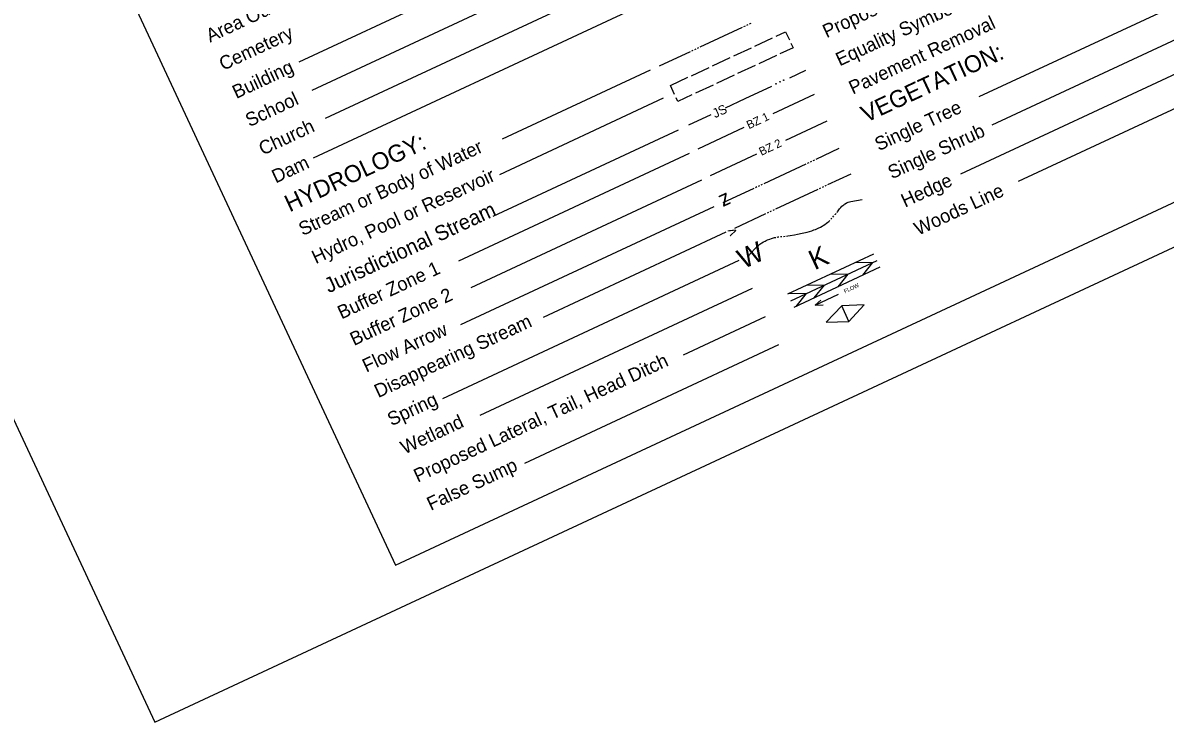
# Model space of a CAD drawing. Extents: x 885291.5 to 885341.7, y 651350.6 to 651393.5.
# Drawn here: x 885301.03 to 885319.4, y 651350.6 to 651361.84 of the extents above; entities that cross this region are included whole.
import ezdxf

# ---------------------------------------------------------------- set-up
doc = ezdxf.new("R2010")
doc.units = 0
doc.layers.add('Sheet Symbology CELL', color=7, linetype='Continuous')
doc.layers.add('Stewart Plot Border Xerox6279 and LJ5000', color=7, linetype='Continuous')

msp = doc.modelspace()

# ---------------------------------------------------------------- linework, layer by layer
at = {"layer": 'Sheet Symbology CELL'}
for p, q in [((885310.171, 651363.407), (885305.464, 651361.212)), ((885310.382, 651362.954), (885305.676, 651360.759)), ((885310.593, 651362.5), (885305.887, 651360.306)), ((885320.502, 651362.567), (885316.398, 651360.653)), ((885320.713, 651362.113), (885316.61, 651360.2)), ((885310.805, 651362.047), (885305.697, 651359.666)), ((885311.921, 651361.459), (885312.601, 651361.776)), ((885312.624, 651361.787), (885312.646, 651361.797)), ((885312.669, 651361.808), (885312.692, 651361.818)), ((885312.714, 651361.829), (885312.737, 651361.839)), ((885312.799, 651361.471), (885313.083, 651361.603)), ((885320.925, 651361.66), (885316.106, 651359.413)), ((885311.264, 651361.152), (885311.763, 651361.385)), ((885311.785, 651361.396), (885311.808, 651361.406)), ((885311.831, 651361.417), (885311.853, 651361.427)), ((885311.876, 651361.438), (885311.899, 651361.449)), ((885312.46, 651361.312), (885312.743, 651361.444)), ((885312.12, 651361.154), (885312.403, 651361.286)), ((885313.145, 651361.32), (885312.862, 651361.188)), ((885321.136, 651361.207), (885317.032, 651359.293)), ((885311.116, 651361.084), (885308.737, 651359.974)), ((885311.78, 651360.995), (885312.063, 651361.127)), ((885312.465, 651361.003), (885312.182, 651360.871)), ((885312.805, 651361.161), (885312.522, 651361.029)), ((885311.44, 651360.837), (885311.723, 651360.969)), ((885311.507, 651360.694), (885311.44, 651360.837)), ((885312.126, 651360.844), (885311.842, 651360.712)), ((885311.327, 651360.631), (885308.69, 651359.401)), ((885313.754, 651360.692), (885313.09, 651360.383)), ((885313.954, 651360.262), (885313.29, 651359.953)), ((885311.566, 651360.119), (885308.584, 651358.728)), ((885311.885, 651359.821), (885312.628, 651360.167)), ((885311.742, 651359.742), (885308.031, 651358.012)), ((885312.085, 651359.391), (885312.828, 651359.737)), ((885313.784, 651359.653), (885314.157, 651359.827)), ((885312.946, 651359.262), (885313.625, 651359.579)), ((885313.648, 651359.59), (885313.671, 651359.6)), ((885313.693, 651359.611), (885313.716, 651359.622)), ((885313.739, 651359.632), (885313.761, 651359.643)), ((885313.975, 651359.243), (885314.349, 651359.417)), ((885311.941, 651359.314), (885308.231, 651357.584)), ((885312.288, 651358.956), (885312.787, 651359.188)), ((885312.81, 651359.199), (885312.832, 651359.21)), ((885312.855, 651359.22), (885312.878, 651359.231)), ((885312.9, 651359.241), (885312.923, 651359.252)), ((885313.137, 651358.852), (885313.817, 651359.169)), ((885313.839, 651359.179), (885313.862, 651359.19)), ((885313.885, 651359.201), (885313.907, 651359.211)), ((885313.93, 651359.222), (885313.953, 651359.232)), ((885312.14, 651358.887), (885308.066, 651356.987)), ((885312.479, 651358.545), (885312.978, 651358.778)), ((885313.001, 651358.788), (885313.024, 651358.799)), ((885313.046, 651358.81), (885313.069, 651358.82)), ((885313.092, 651358.831), (885313.114, 651358.841)), ((885314.02, 651358.685), (885314.037, 651358.703)), ((885314.054, 651358.721), (885314.071, 651358.74)), ((885312.332, 651358.476), (885309.397, 651357.108)), ((885313.259, 651358.411), (885313.284, 651358.414)), ((885313.331, 651357.487), (885314.713, 651358.132)), ((885312.543, 651358.023), (885307.774, 651355.799)), ((885313.375, 651357.376), (885314.764, 651358.023)), ((885313.43, 651357.273), (885314.813, 651357.918)), ((885314.425, 651357.997), (885314.693, 651357.99)), ((885314.693, 651357.99), (885314.531, 651357.786)), ((885314.023, 651357.81), (885314.296, 651357.805)), ((885314.296, 651357.805), (885314.131, 651357.6)), ((885312.754, 651357.57), (885308.377, 651355.529)), ((885313.351, 651357.497), (885313.623, 651357.491)), ((885313.623, 651357.491), (885313.457, 651357.285)), ((885313.639, 651357.631), (885313.912, 651357.626)), ((885313.912, 651357.626), (885313.746, 651357.42)), ((885313.767, 651357.306), (885314.144, 651357.482)), ((885313.767, 651357.306), (885313.861, 651357.387)), ((885313.767, 651357.306), (885313.896, 651357.312)), ((885314.555, 651357.309), (885314.195, 651357.293)), ((885314.312, 651357.043), (885314.555, 651357.309)), ((885314.195, 651357.293), (885313.943, 651357.03)), ((885314.312, 651357.043), (885314.195, 651357.293)), ((885312.966, 651357.117), (885311.648, 651356.502)), ((885313.943, 651357.03), (885314.312, 651357.043)), ((885313.177, 651356.664), (885309.092, 651354.759))]:
    msp.add_line(p, q, dxfattribs=at)
msp.add_lwpolyline([(885329.923, 651392.736), (885295.937, 651376.888), (885307.02, 651353.12), (885341.006, 651368.969)], close=True, dxfattribs=at)
for points in [[(885313.139, 651361.629), (885313.294, 651361.701), (885313.354, 651361.573)], [(885313.38, 651361.516), (885313.414, 651361.445), (885313.202, 651361.346)], [(885313.359, 651360.96), (885313.618, 651361.081)], [(885312.643, 651360.626), (885313.074, 651360.827)], [(885311.786, 651360.686), (885311.56, 651360.58), (885311.533, 651360.637)], [(885312.326, 651360.478), (885312.643, 651360.626)], [(885311.736, 651360.203), (885312.098, 651360.372)], [(885314.12, 651358.797), (885314.128, 651358.807), (885314.162, 651358.851), (885314.179, 651358.873), (885314.198, 651358.894), (885314.213, 651358.908), (885314.227, 651358.919), (885314.24, 651358.929), (885314.252, 651358.936), (885314.273, 651358.948), (885314.289, 651358.956), (885314.302, 651358.961), (885314.321, 651358.967), (885314.341, 651358.971), (885314.432, 651358.986), (885314.522, 651359.001)], [(885314.088, 651358.758), (885314.091, 651358.762), (885314.104, 651358.777)], [(885313.309, 651358.416), (885313.329, 651358.419), (885313.365, 651358.424), (885313.434, 651358.436), (885313.485, 651358.446), (885313.561, 651358.462), (885313.638, 651358.48), (885313.679, 651358.491), (885313.716, 651358.502), (885313.747, 651358.513), (885313.775, 651358.523), (885313.798, 651358.532), (885313.819, 651358.541), (885313.854, 651358.558), (885313.879, 651358.572), (885313.898, 651358.584), (885313.925, 651358.601), (885313.951, 651358.621), (885313.97, 651358.637), (885313.986, 651358.652), (885314.002, 651358.667)], [(885312.691, 651358.092), (885312.743, 651358.149), (885312.795, 651358.206), (885312.808, 651358.22), (885312.832, 651358.243), (885312.851, 651358.26), (885312.881, 651358.283), (885312.911, 651358.304), (885312.938, 651358.321), (885312.962, 651358.334), (885312.983, 651358.345), (885313.003, 651358.354), (885313.037, 651358.368), (885313.064, 651358.377), (885313.084, 651358.383), (885313.114, 651358.391), (885313.136, 651358.395)], [(885313.16, 651358.399), (885313.172, 651358.401), (885313.185, 651358.403)], [(885313.21, 651358.406), (885313.221, 651358.407), (885313.235, 651358.409)]]:
    msp.add_lwpolyline(points, dxfattribs=at)
for centre in [(885313.138, 651360.864), (885313.205, 651360.896), (885313.263, 651360.923)]:
    msp.add_ellipse(centre, major_axis=(-0.00208, 0.00446), ratio=0.938496, dxfattribs=at)
at = {"layer": 'Stewart Plot Border Xerox6279 and LJ5000'}
msp.add_lwpolyline([(885303.148, 651350.597), (885341.666, 651368.559), (885330.044, 651393.482), (885291.526, 651375.521)], close=True, dxfattribs=at)

# ---------------------------------------------------------------- texts
at = {"layer": 'Sheet Symbology CELL'}
for s, height, rotation, p in [('Proposed Cable Guiderail', 0.21875, 25, (885313.952, 651361.596)), ('Area Outline', 0.21875, 25, (885304.037, 651361.525)), ('Equality Symbol', 0.21875, 25, (885314.163, 651361.143)), ('Pavement Removal', 0.21875, 25, (885314.374, 651360.689)), ('Cemetery', 0.2188, 25, (885304.248, 651361.072)), ('VEGETATION:', 0.275, 25, (885314.586, 651360.234)), ('Building', 0.2188, 25, (885304.46, 651360.619)), ('School', 0.2188, 25, (885304.671, 651360.166)), ('JS', 0.1476, 25, (885312.159, 651360.309)), ('Single Tree', 0.21875, 25, (885314.791, 651359.779)), ('Church', 0.2188, 25, (885304.885, 651359.709)), ('BZ 1', 0.1329, 25, (885312.703, 651360.133)), ('Single Shrub', 0.21875, 25, (885315.002, 651359.326)), ('HYDROLOGY:', 0.275, 25, (885305.318, 651358.795)), ('Stream or Body of Water', 0.21875, 25, (885305.527, 651358.415)), ('BZ 2', 0.1329, 25, (885312.903, 651359.705)), ('Dam', 0.2188, 25, (885305.094, 651359.26)), ('Hydro, Pool or Reservoir', 0.21875, 25, (885305.738, 651357.962)), ('Hedge', 0.2188, 25, (885315.214, 651358.872)), ('Woods Line', 0.2188, 25, (885315.425, 651358.419)), ('z', 0.25, 205, (885312.349, 651359.122)), ('Jurisdictional Stream', 0.24115, 25, (885305.947, 651357.493)), ('v', 0.165, 114.7591, (885312.519, 651358.461)), ('W', 0.319, 25, (885312.614, 651357.88)), ('K', 0.319, 25, (885313.76, 651357.863)), ('Buffer Zone 1', 0.21875, 25, (885306.152, 651357.073)), ('Buffer Zone 2', 0.21875, 25, (885306.352, 651356.646)), ('FLOW', 0.0648, 25, (885314.248, 651357.493)), ('Flow Arrow', 0.2188, 25, (885306.551, 651356.218)), ('Disappearing Stream', 0.21875, 25, (885306.743, 651355.808)), ('Proposed Lateral, Tail, Head Ditch', 0.21875, 25, (885307.376, 651354.448)), ('Spring', 0.2188, 25, (885306.954, 651355.355)), ('Wetland', 0.2188, 25, (885307.165, 651354.901)), ('False Sump', 0.2188, 25, (885307.588, 651353.995))]:
    msp.add_text(s, height=height, rotation=rotation, dxfattribs=at).set_placement(p)

doc.saveas('drawing.dxf')
